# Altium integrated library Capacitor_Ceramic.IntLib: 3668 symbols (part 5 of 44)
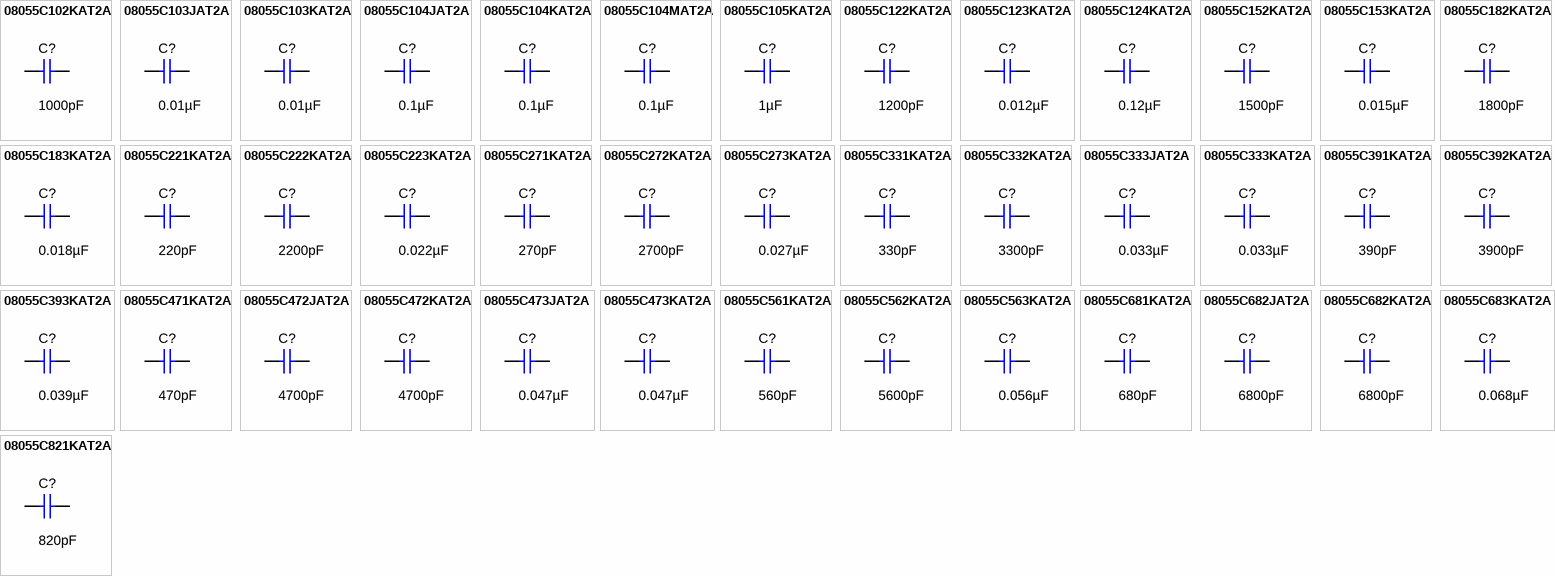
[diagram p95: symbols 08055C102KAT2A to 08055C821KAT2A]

## 08055C681KAT2A
designator C?  ValueDisplayed: 680pF  (hidden comment: 08055C681KAT2A)
CAP, CERM, 680 pF, 50 V,+/- 10%, X7R, 0805; Manufacturer: AVX; Polarized: N; CompType: Capacitor; Value: 680pF; U/M: EA; Cap_F: 0.00000000068; Tolerance_%: 10; ESR_ohm: 0.364; Value1: 0.364 ohm; VDC_V: 50; Value2: 50V; TaMin_C: -55; TaMax_C: 125; Cap_Case: 0805; SizeArea_mm2: 2.5; SizeAreaWB_mm2: 6.75; SizeX_mm: 2; SizeY_mm: 1.25; SizeZ_mm: 1.45; AEC Category: Q200; Green_Lifecycle: Not Set; Green_REACh: Incomplete
signal-integrity model Cap
simulation model Cap
footprint 0805_HV
footprint 0805_HV1
footprint 0805
footprint 0805M
footprint 0805L
pins: 1, 2

## 08055C682JAT2A
designator C?  ValueDisplayed: 6800pF  (hidden comment: 08055C682JAT2A)
CAP, CERM, 6800 pF, 50 V,+/- 5%, X7R, 0805; Manufacturer: AVX; Polarized: N; CompType: Capacitor; Value: 6800pF; U/M: EA; Cap_F: 0.0000000068; Tolerance_%: 5; ESR_ohm: 0.096; Value1: 0.096 ohm; VDC_V: 50; Value2: 50V; TaMin_C: -55; TaMax_C: 125; Cap_Case: 0805; SizeArea_mm2: 2.5; SizeAreaWB_mm2: 6.75; SizeX_mm: 2; SizeY_mm: 1.25; SizeZ_mm: 1.45; AEC Category: Q200; Green_Lifecycle: Not Set; Green_REACh: Incomplete
signal-integrity model Cap
simulation model Cap
footprint 0805_HV
footprint 0805_HV1
footprint 0805
footprint 0805M
footprint 0805L
pins: 1, 2

## 08055C682KAT2A
designator C?  ValueDisplayed: 6800pF  (hidden comment: 08055C682KAT2A)
CAP, CERM, 6800 pF, 50 V,+/- 10%, X7R, 0805; Manufacturer: AVX; Polarized: N; CompType: Capacitor; Value: 6800pF; U/M: EA; Cap_F: 0.0000000068; Tolerance_%: 10; ESR_ohm: 0.096; Value1: 0.096 ohm; VDC_V: 50; Value2: 50V; TaMin_C: -55; TaMax_C: 125; Cap_Case: 0805; SizeArea_mm2: 2.5; SizeAreaWB_mm2: 6.75; SizeX_mm: 2; SizeY_mm: 1.25; SizeZ_mm: 1.45; AEC Category: Q200; Green_Lifecycle: Not Set; Green_REACh: Incomplete
signal-integrity model Cap
simulation model Cap
footprint 0805_HV
footprint 0805_HV1
footprint 0805
footprint 0805M
footprint 0805L
pins: 1, 2

## 08055C683KAT2A
designator C?  ValueDisplayed: 0.068µF  (hidden comment: 08055C683KAT2A)
CAP, CERM, 0.068 µF, 50 V,+/- 10%, X7R, 0805; Manufacturer: AVX; Polarized: N; CompType: Capacitor; Value: 0.068uF; U/M: EA; Cap_F: 0.000000068; Tolerance_%: 10; ESR_ohm: 0.029; Value1: 0.029 ohm; VDC_V: 50; Value2: 50V; TaMin_C: -55; TaMax_C: 125; Cap_Case: 0805; SizeArea_mm2: 2.5; SizeAreaWB_mm2: 6.75; SizeX_mm: 2; SizeY_mm: 1.25; SizeZ_mm: 1.45; AEC Category: Q200; Green_Lifecycle: Not Set; Green_REACh: Incomplete
signal-integrity model Cap
simulation model Cap
footprint 0805_HV
footprint 0805_HV1
footprint 0805
footprint 0805M
footprint 0805L
pins: 1, 2

## 08055C821KAT2A
designator C?  ValueDisplayed: 820pF  (hidden comment: 08055C821KAT2A)
CAP, CERM, 820 pF, 50 V,+/- 10%, X7R, 0805; Manufacturer: AVX; Polarized: N; CompType: Capacitor; Value: 820pF; U/M: EA; Cap_F: 0.00000000082; Tolerance_%: 10; ESR_ohm: 0.326; Value1: 0.326 ohm; VDC_V: 50; Value2: 50V; TaMin_C: -55; TaMax_C: 125; Cap_Case: 0805; SizeArea_mm2: 2.5; SizeAreaWB_mm2: 6.75; SizeX_mm: 2; SizeY_mm: 1.25; SizeZ_mm: 1.45; AEC Category: Q200; Green_Lifecycle: Not Set; Green_REACh: Incomplete
signal-integrity model Cap
simulation model Cap
footprint 0805_HV
footprint 0805_HV1
footprint 0805
footprint 0805M
footprint 0805L
pins: 1, 2

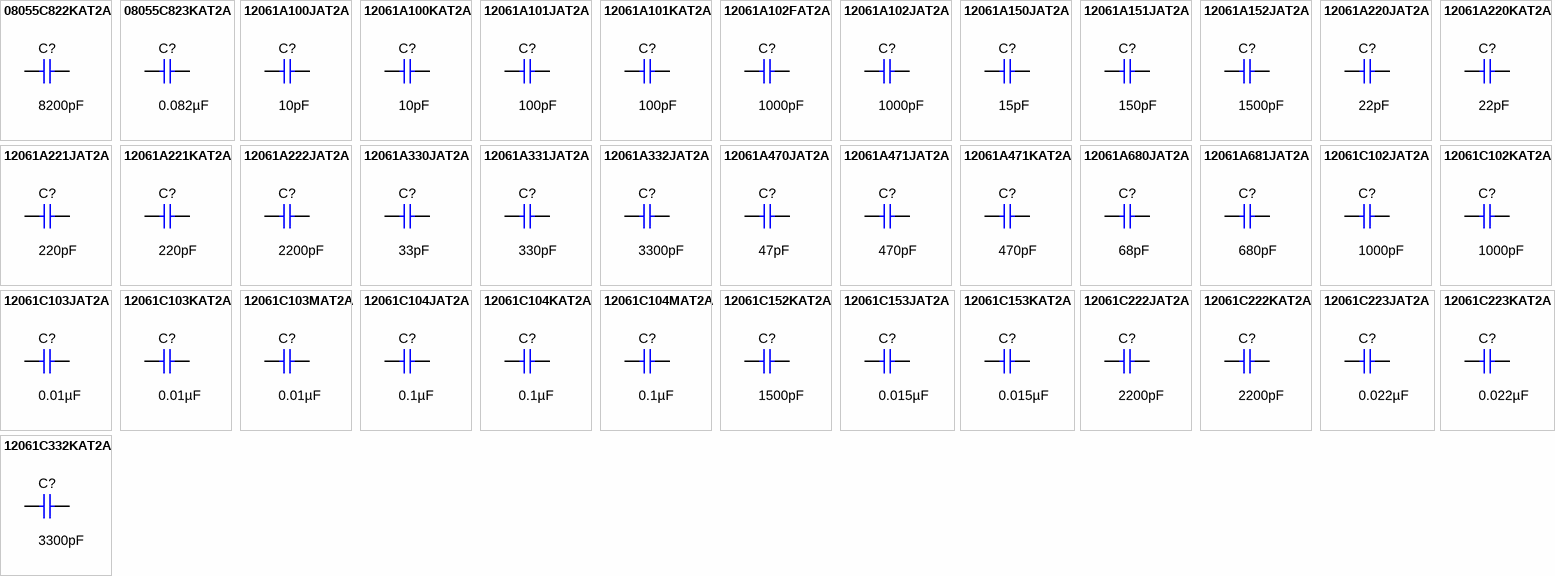
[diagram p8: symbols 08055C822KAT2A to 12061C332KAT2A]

## 08055C822KAT2A
designator C?  ValueDisplayed: 8200pF  (hidden comment: 08055C822KAT2A)
CAP, CERM, 8200 pF, 50 V,+/- 10%, X7R, 0805; Manufacturer: AVX; Polarized: N; CompType: Capacitor; Value: 8200pF; U/M: EA; Cap_F: 0.0000000082; Tolerance_%: 10; ESR_ohm: 0.087; Value1: 0.087 ohm; VDC_V: 50; Value2: 50V; TaMin_C: -55; TaMax_C: 125; Cap_Case: 0805; SizeArea_mm2: 2.5; SizeAreaWB_mm2: 6.75; SizeX_mm: 2; SizeY_mm: 1.25; SizeZ_mm: 1.45; AEC Category: Q200; Green_Lifecycle: Not Set; Green_REACh: Incomplete
signal-integrity model Cap
simulation model Cap
footprint 0805_HV
footprint 0805_HV1
footprint 0805
footprint 0805M
footprint 0805L
pins: 1, 2

## 08055C823KAT2A
designator C?  ValueDisplayed: 0.082µF  (hidden comment: 08055C823KAT2A)
CAP, CERM, 0.082 µF, 50 V,+/- 10%, X7R, 0805; Manufacturer: AVX; Polarized: N; CompType: Capacitor; Value: 0.082uF; U/M: EA; Cap_F: 0.000000082; Tolerance_%: 10; ESR_ohm: 0.026; Value1: 0.026 ohm; VDC_V: 50; Value2: 50V; TaMin_C: -55; TaMax_C: 125; Cap_Case: 0805; SizeArea_mm2: 2.5; SizeAreaWB_mm2: 6.75; SizeX_mm: 2; SizeY_mm: 1.25; SizeZ_mm: 1.45; AEC Category: Q200; Green_Lifecycle: Active; Green_REACh: Passed
signal-integrity model Cap
simulation model Cap
footprint 0805_HV
footprint 0805_HV1
footprint 0805
footprint 0805M
footprint 0805L
pins: 1, 2

## 12061A100JAT2A
designator C?  ValueDisplayed: 10pF  (hidden comment: 12061A100JAT2A)
CAP, CERM, 10 pF, 100 V,+/- 5%, C0G/NP0, 1206; Manufacturer: AVX; Polarized: N; CompType: Capacitor; Value: 10pF; U/M: EA; Cap_F: 0.00000000001; Tolerance_%: 5; ESR_ohm: 2.925; Value1: 2.925 ohm; VDC_V: 100; Value2: 100V; TaMin_C: -55; TaMax_C: 125; Cap_Case: 1206; SizeArea_mm2: 5.12; SizeAreaWB_mm2: 10.92; SizeX_mm: 3.2; SizeY_mm: 1.6; SizeZ_mm: 1.35; AEC Category: Q200; Green_Lifecycle: Not Set; Green_REACh: Incomplete
signal-integrity model Cap
simulation model Cap
footprint 1206
footprint 1206M
footprint 1206L
pins: 1, 2

## 12061A100KAT2A
designator C?  ValueDisplayed: 10pF  (hidden comment: 12061A100KAT2A)
CAP, CERM, 10 pF, 100 V,+/- 10%, C0G/NP0, 1206; Manufacturer: AVX; Polarized: N; CompType: Capacitor; Value: 10pF; U/M: EA; Cap_F: 0.00000000001; Tolerance_%: 10; ESR_ohm: 2.925; Value1: 2.925 ohm; VDC_V: 100; Value2: 100V; TaMin_C: -55; TaMax_C: 125; Cap_Case: 1206; SizeArea_mm2: 5.12; SizeAreaWB_mm2: 10.92; SizeX_mm: 3.2; SizeY_mm: 1.6; SizeZ_mm: 1.35; AEC Category: Q200; Green_Lifecycle: Not Set; Green_REACh: Incomplete
signal-integrity model Cap
simulation model Cap
footprint 1206
footprint 1206M
footprint 1206L
pins: 1, 2

## 12061A101JAT2A
designator C?  ValueDisplayed: 100pF  (hidden comment: 12061A101JAT2A)
CAP, CERM, 100 pF, 100 V,+/- 5%, C0G/NP0, 1206; Manufacturer: AVX; Polarized: N; CompType: Capacitor; Value: 100pF; U/M: EA; Cap_F: 0.0000000001; Tolerance_%: 5; ESR_ohm: 0.701; Value1: 0.701 ohm; VDC_V: 100; Value2: 100V; TaMin_C: -55; TaMax_C: 125; Cap_Case: 1206; SizeArea_mm2: 5.12; SizeAreaWB_mm2: 10.92; SizeX_mm: 3.2; SizeY_mm: 1.6; SizeZ_mm: 1.35; AEC Category: Q200; Green_Lifecycle: Active; Green_REACh: Passed
signal-integrity model Cap
simulation model Cap
footprint 1206
footprint 1206M
footprint 1206L
pins: 1, 2

## 12061A101KAT2A
designator C?  ValueDisplayed: 100pF  (hidden comment: 12061A101KAT2A)
CAP, CERM, 100 pF, 100 V,+/- 10%, C0G/NP0, 1206; Manufacturer: AVX; Polarized: N; CompType: Capacitor; Value: 100pF; U/M: EA; Cap_F: 0.0000000001; Tolerance_%: 10; ESR_ohm: 0.701; Value1: 0.701 ohm; VDC_V: 100; Value2: 100V; TaMin_C: -55; TaMax_C: 125; Cap_Case: 1206; SizeArea_mm2: 5.12; SizeAreaWB_mm2: 10.92; SizeX_mm: 3.2; SizeY_mm: 1.6; SizeZ_mm: 1.35; AEC Category: Q200; Green_Lifecycle: Not Set; Green_REACh: Incomplete
signal-integrity model Cap
simulation model Cap
footprint 1206
footprint 1206M
footprint 1206L
pins: 1, 2

## 12061A102FAT2A
designator C?  ValueDisplayed: 1000pF  (hidden comment: 12061A102FAT2A)
CAP, CERM, 1000 pF, 100 V,+/- 1%, C0G/NP0, 1206; Manufacturer: AVX; Polarized: N; CompType: Capacitor; Value: 1000pF; U/M: EA; Cap_F: 0.000000001; Tolerance_%: 1; ESR_ohm: 0.238; Value1: 0.238 ohm; VDC_V: 100; Value2: 100V; TaMin_C: -55; TaMax_C: 125; Cap_Case: 1206; SizeArea_mm2: 5.12; SizeAreaWB_mm2: 10.92; SizeX_mm: 3.2; SizeY_mm: 1.6; SizeZ_mm: 1.35; AEC Category: Q200; Green_Lifecycle: Not Set; Green_REACh: Incomplete
signal-integrity model Cap
simulation model Cap
footprint 1206
footprint 1206M
footprint 1206L
pins: 1, 2

## 12061A102JAT2A
designator C?  ValueDisplayed: 1000pF  (hidden comment: 12061A102JAT2A)
CAP, CERM, 1000 pF, 100 V,+/- 5%, C0G/NP0, 1206; Manufacturer: AVX; Polarized: N; CompType: Capacitor; Value: 1000pF; U/M: EA; Cap_F: 0.000000001; Tolerance_%: 5; ESR_ohm: 0.238; Value1: 0.238 ohm; VDC_V: 100; Value2: 100V; TaMin_C: -55; TaMax_C: 125; Cap_Case: 1206; SizeArea_mm2: 5.12; SizeAreaWB_mm2: 10.92; SizeX_mm: 3.2; SizeY_mm: 1.6; SizeZ_mm: 1.35; AEC Category: Q200; Green_Lifecycle: Active; Green_REACh: Passed
signal-integrity model Cap
simulation model Cap
footprint 1206
footprint 1206M
footprint 1206L
pins: 1, 2

## 12061A150JAT2A
designator C?  ValueDisplayed: 15pF  (hidden comment: 12061A150JAT2A)
CAP, CERM, 15 pF, 100 V,+/- 5%, C0G/NP0, 1206; Manufacturer: AVX; Polarized: N; CompType: Capacitor; Value: 15pF; U/M: EA; Cap_F: 0.000000000015; Tolerance_%: 5; ESR_ohm: 2.241; Value1: 2.241 ohm; VDC_V: 100; Value2: 100V; TaMin_C: -55; TaMax_C: 125; Cap_Case: 1206; SizeArea_mm2: 5.12; SizeAreaWB_mm2: 10.92; SizeX_mm: 3.2; SizeY_mm: 1.6; SizeZ_mm: 1.35; AEC Category: Q200; Green_Lifecycle: Not Set; Green_REACh: Incomplete
signal-integrity model Cap
simulation model Cap
footprint 1206
footprint 1206M
footprint 1206L
pins: 1, 2

## 12061A151JAT2A
designator C?  ValueDisplayed: 150pF  (hidden comment: 12061A151JAT2A)
CAP, CERM, 150 pF, 100 V,+/- 5%, C0G/NP0, 1206; Manufacturer: AVX; Polarized: N; CompType: Capacitor; Value: 150pF; U/M: EA; Cap_F: 0.00000000015; Tolerance_%: 5; ESR_ohm: 0.573; Value1: 0.573 ohm; VDC_V: 100; Value2: 100V; TaMin_C: -55; TaMax_C: 125; Cap_Case: 1206; SizeArea_mm2: 5.12; SizeAreaWB_mm2: 10.92; SizeX_mm: 3.2; SizeY_mm: 1.6; SizeZ_mm: 1.35; AEC Category: Q200; Green_Lifecycle: Not Set; Green_REACh: Incomplete
signal-integrity model Cap
simulation model Cap
footprint 1206
footprint 1206M
footprint 1206L
pins: 1, 2

## 12061A152JAT2A
designator C?  ValueDisplayed: 1500pF  (hidden comment: 12061A152JAT2A)
CAP, CERM, 1500 pF, 100 V,+/- 5%, C0G/NP0, 1206; Manufacturer: AVX; Polarized: N; CompType: Capacitor; Value: 1500pF; U/M: EA; Cap_F: 0.0000000015; Tolerance_%: 5; ESR_ohm: 0.201; Value1: 0.201 ohm; VDC_V: 100; Value2: 100V; TaMin_C: -55; TaMax_C: 125; Cap_Case: 1206; SizeArea_mm2: 5.12; SizeAreaWB_mm2: 10.92; SizeX_mm: 3.2; SizeY_mm: 1.6; SizeZ_mm: 1.35; AEC Category: Q200; Green_Lifecycle: Not Set; Green_REACh: Incomplete
signal-integrity model Cap
simulation model Cap
footprint 1206
footprint 1206M
footprint 1206L
pins: 1, 2

## 12061A220JAT2A
designator C?  ValueDisplayed: 22pF  (hidden comment: 12061A220JAT2A)
CAP, CERM, 22 pF, 100 V,+/- 5%, C0G/NP0, 1206; Manufacturer: AVX; Polarized: N; CompType: Capacitor; Value: 22pF; U/M: EA; Cap_F: 0.000000000022; Tolerance_%: 5; ESR_ohm: 1.753; Value1: 1.753 ohm; VDC_V: 100; Value2: 100V; TaMin_C: -55; TaMax_C: 125; Cap_Case: 1206; SizeArea_mm2: 5.12; SizeAreaWB_mm2: 10.92; SizeX_mm: 3.2; SizeY_mm: 1.6; SizeZ_mm: 1.35; AEC Category: Q200; Green_Lifecycle: Not Set; Green_REACh: Incomplete
signal-integrity model Cap
simulation model Cap
footprint 1206
footprint 1206M
footprint 1206L
pins: 1, 2

## 12061A220KAT2A
designator C?  ValueDisplayed: 22pF  (hidden comment: 12061A220KAT2A)
CAP, CERM, 22 pF, 100 V,+/- 10%, C0G/NP0, 1206; Manufacturer: AVX; Polarized: N; CompType: Capacitor; Value: 22pF; U/M: EA; Cap_F: 0.000000000022; Tolerance_%: 10; ESR_ohm: 1.753; Value1: 1.753 ohm; VDC_V: 100; Value2: 100V; TaMin_C: -55; TaMax_C: 125; Cap_Case: 1206; SizeArea_mm2: 5.12; SizeAreaWB_mm2: 10.92; SizeX_mm: 3.2; SizeY_mm: 1.6; SizeZ_mm: 1.35; AEC Category: Q200; Green_Lifecycle: Not Set; Green_REACh: Incomplete
signal-integrity model Cap
simulation model Cap
footprint 1206
footprint 1206M
footprint 1206L
pins: 1, 2

## 12061A221JAT2A
designator C?  ValueDisplayed: 220pF  (hidden comment: 12061A221JAT2A)
CAP, CERM, 220 pF, 100 V,+/- 5%, C0G/NP0, 1206; Manufacturer: AVX; Polarized: N; CompType: Capacitor; Value: 220pF; U/M: EA; Cap_F: 0.00000000022; Tolerance_%: 5; ESR_ohm: 0.475; Value1: 0.475 ohm; VDC_V: 100; Value2: 100V; TaMin_C: -55; TaMax_C: 125; Cap_Case: 1206; SizeArea_mm2: 5.12; SizeAreaWB_mm2: 10.92; SizeX_mm: 3.2; SizeY_mm: 1.6; SizeZ_mm: 1.35; AEC Category: Q200; Green_Lifecycle: Active; Green_REACh: Passed
signal-integrity model Cap
simulation model Cap
footprint 1206
footprint 1206M
footprint 1206L
pins: 1, 2

## 12061A221KAT2A
designator C?  ValueDisplayed: 220pF  (hidden comment: 12061A221KAT2A)
CAP, CERM, 220 pF, 100 V,+/- 10%, C0G/NP0, 1206; Manufacturer: AVX; Polarized: N; CompType: Capacitor; Value: 220pF; U/M: EA; Cap_F: 0.00000000022; Tolerance_%: 10; ESR_ohm: 0.475; Value1: 0.475 ohm; VDC_V: 100; Value2: 100V; TaMin_C: -55; TaMax_C: 125; Cap_Case: 1206; SizeArea_mm2: 5.12; SizeAreaWB_mm2: 10.92; SizeX_mm: 3.2; SizeY_mm: 1.6; SizeZ_mm: 1.35; AEC Category: Q200; Green_Lifecycle: Not Set; Green_REACh: Incomplete
signal-integrity model Cap
simulation model Cap
footprint 1206
footprint 1206M
footprint 1206L
pins: 1, 2

## 12061A222JAT2A
designator C?  ValueDisplayed: 2200pF  (hidden comment: 12061A222JAT2A)
CAP, CERM, 2200 pF, 100 V,+/- 5%, C0G/NP0, 1206; Manufacturer: AVX; Polarized: N; CompType: Capacitor; Value: 2200pF; U/M: EA; Cap_F: 0.0000000022; Tolerance_%: 5; ESR_ohm: 0.173; Value1: 0.173 ohm; VDC_V: 100; Value2: 100V; TaMin_C: -55; TaMax_C: 125; Cap_Case: 1206; SizeArea_mm2: 5.12; SizeAreaWB_mm2: 10.92; SizeX_mm: 3.2; SizeY_mm: 1.6; SizeZ_mm: 1.35; AEC Category: Q200; Green_Lifecycle: Not Set; Green_REACh: Incomplete
signal-integrity model Cap
simulation model Cap
footprint 1206
footprint 1206M
footprint 1206L
pins: 1, 2

## 12061A330JAT2A
designator C?  ValueDisplayed: 33pF  (hidden comment: 12061A330JAT2A)
CAP, CERM, 33 pF, 100 V,+/- 5%, C0G/NP0, 1206; Manufacturer: AVX; Polarized: N; CompType: Capacitor; Value: 33pF; U/M: EA; Cap_F: 0.000000000033; Tolerance_%: 5; ESR_ohm: 1.359; Value1: 1.359 ohm; VDC_V: 100; Value2: 100V; TaMin_C: -55; TaMax_C: 125; Cap_Case: 1206; SizeArea_mm2: 5.12; SizeAreaWB_mm2: 10.92; SizeX_mm: 3.2; SizeY_mm: 1.6; SizeZ_mm: 1.35; AEC Category: Q200; Green_Lifecycle: Not Set; Green_REACh: Incomplete
signal-integrity model Cap
simulation model Cap
footprint 1206
footprint 1206M
footprint 1206L
pins: 1, 2

## 12061A331JAT2A
designator C?  ValueDisplayed: 330pF  (hidden comment: 12061A331JAT2A)
CAP, CERM, 330 pF, 100 V,+/- 5%, C0G/NP0, 1206; Manufacturer: AVX; Polarized: N; CompType: Capacitor; Value: 330pF; U/M: EA; Cap_F: 0.00000000033; Tolerance_%: 5; ESR_ohm: 0.392; Value1: 0.392 ohm; VDC_V: 100; Value2: 100V; TaMin_C: -55; TaMax_C: 125; Cap_Case: 1206; SizeArea_mm2: 5.12; SizeAreaWB_mm2: 10.92; SizeX_mm: 3.2; SizeY_mm: 1.6; SizeZ_mm: 1.35; AEC Category: Q200; Green_Lifecycle: Not Set; Green_REACh: Incomplete
signal-integrity model Cap
simulation model Cap
footprint 1206
footprint 1206M
footprint 1206L
pins: 1, 2

## 12061A332JAT2A
designator C?  ValueDisplayed: 3300pF  (hidden comment: 12061A332JAT2A)
CAP, CERM, 3300 pF, 100 V,+/- 5%, C0G/NP0, 1206; Manufacturer: AVX; Polarized: N; CompType: Capacitor; Value: 3300pF; U/M: EA; Cap_F: 0.0000000033; Tolerance_%: 5; ESR_ohm: 0.149; Value1: 0.149 ohm; VDC_V: 100; Value2: 100V; TaMin_C: -55; TaMax_C: 125; Cap_Case: 1206; SizeArea_mm2: 5.12; SizeAreaWB_mm2: 10.92; SizeX_mm: 3.2; SizeY_mm: 1.6; SizeZ_mm: 1.35; AEC Category: Q200; Green_Lifecycle: Not Set; Green_REACh: Incomplete
signal-integrity model Cap
simulation model Cap
footprint 1206
footprint 1206M
footprint 1206L
pins: 1, 2

## 12061A470JAT2A
designator C?  ValueDisplayed: 47pF  (hidden comment: 12061A470JAT2A)
CAP, CERM, 47 pF, 100 V,+/- 5%, C0G/NP0, 1206; Manufacturer: AVX; Polarized: N; CompType: Capacitor; Value: 47pF; U/M: EA; Cap_F: 0.000000000047; Tolerance_%: 5; ESR_ohm: 1.093; Value1: 1.093 ohm; VDC_V: 100; Value2: 100V; TaMin_C: -55; TaMax_C: 125; Cap_Case: 1206; SizeArea_mm2: 5.12; SizeAreaWB_mm2: 10.92; SizeX_mm: 3.2; SizeY_mm: 1.6; SizeZ_mm: 1.35; AEC Category: Q200; Green_Lifecycle: Not Set; Green_REACh: Incomplete
signal-integrity model Cap
simulation model Cap
footprint 1206
footprint 1206M
footprint 1206L
pins: 1, 2

## 12061A471JAT2A
designator C?  ValueDisplayed: 470pF  (hidden comment: 12061A471JAT2A)
CAP, CERM, 470 pF, 100 V,+/- 5%, C0G/NP0, 1206; Manufacturer: AVX; Polarized: N; CompType: Capacitor; Value: 470pF; U/M: EA; Cap_F: 0.00000000047; Tolerance_%: 5; ESR_ohm: 0.332; Value1: 0.332 ohm; VDC_V: 100; Value2: 100V; TaMin_C: -55; TaMax_C: 125; Cap_Case: 1206; SizeArea_mm2: 5.12; SizeAreaWB_mm2: 10.92; SizeX_mm: 3.2; SizeY_mm: 1.6; SizeZ_mm: 1.35; AEC Category: Q200; Green_Lifecycle: Not Set; Green_REACh: Incomplete
signal-integrity model Cap
simulation model Cap
footprint 1206
footprint 1206M
footprint 1206L
pins: 1, 2

## 12061A471KAT2A
designator C?  ValueDisplayed: 470pF  (hidden comment: 12061A471KAT2A)
CAP, CERM, 470 pF, 100 V,+/- 10%, C0G/NP0, 1206; Manufacturer: AVX; Polarized: N; CompType: Capacitor; Value: 470pF; U/M: EA; Cap_F: 0.00000000047; Tolerance_%: 10; ESR_ohm: 0.332; Value1: 0.332 ohm; VDC_V: 100; Value2: 100V; TaMin_C: -55; TaMax_C: 125; Cap_Case: 1206; SizeArea_mm2: 5.12; SizeAreaWB_mm2: 10.92; SizeX_mm: 3.2; SizeY_mm: 1.6; SizeZ_mm: 1.35; AEC Category: Q200; Green_Lifecycle: Active; Green_REACh: Passed
signal-integrity model Cap
simulation model Cap
footprint 1206
footprint 1206M
footprint 1206L
pins: 1, 2

## 12061A680JAT2A
designator C?  ValueDisplayed: 68pF  (hidden comment: 12061A680JAT2A)
CAP, CERM, 68 pF, 100 V,+/- 5%, C0G/NP0, 1206; Manufacturer: AVX; Polarized: N; CompType: Capacitor; Value: 68pF; U/M: EA; Cap_F: 0.000000000068; Tolerance_%: 5; ESR_ohm: 0.874; Value1: 0.874 ohm; VDC_V: 100; Value2: 100V; TaMin_C: -55; TaMax_C: 125; Cap_Case: 1206; SizeArea_mm2: 5.12; SizeAreaWB_mm2: 10.92; SizeX_mm: 3.2; SizeY_mm: 1.6; SizeZ_mm: 1.35; AEC Category: Q200; Green_Lifecycle: Not Set; Green_REACh: Incomplete
signal-integrity model Cap
simulation model Cap
footprint 1206
footprint 1206M
footprint 1206L
pins: 1, 2

## 12061A681JAT2A
designator C?  ValueDisplayed: 680pF  (hidden comment: 12061A681JAT2A)
CAP, CERM, 680 pF, 100 V,+/- 5%, C0G/NP0, 1206; Manufacturer: AVX; Polarized: N; CompType: Capacitor; Value: 680pF; U/M: EA; Cap_F: 0.00000000068; Tolerance_%: 5; ESR_ohm: 0.281; Value1: 0.281 ohm; VDC_V: 100; Value2: 100V; TaMin_C: -55; TaMax_C: 125; Cap_Case: 1206; SizeArea_mm2: 5.12; SizeAreaWB_mm2: 10.92; SizeX_mm: 3.2; SizeY_mm: 1.6; SizeZ_mm: 1.35; AEC Category: Q200; Green_Lifecycle: Not Set; Green_REACh: Incomplete
signal-integrity model Cap
simulation model Cap
footprint 1206
footprint 1206M
footprint 1206L
pins: 1, 2

## 12061C102JAT2A
designator C?  ValueDisplayed: 1000pF  (hidden comment: 12061C102JAT2A)
CAP, CERM, 1000 pF, 100 V,+/- 5%, X7R, 1206; Manufacturer: AVX; Polarized: N; CompType: Capacitor; Value: 1000pF; U/M: EA; Cap_F: 0.000000001; Tolerance_%: 5; ESR_ohm: 0.427; Value1: 0.427 ohm; VDC_V: 100; Value2: 100V; TaMin_C: -55; TaMax_C: 125; Cap_Case: 1206; SizeArea_mm2: 5.12; SizeAreaWB_mm2: 10.92; SizeX_mm: 3.2; SizeY_mm: 1.6; SizeZ_mm: 1.35; AEC Category: Q200; Green_Lifecycle: Not Set; Green_REACh: Incomplete
signal-integrity model Cap
simulation model Cap
footprint 1206
footprint 1206M
footprint 1206L
pins: 1, 2

## 12061C102KAT2A
designator C?  ValueDisplayed: 1000pF  (hidden comment: 12061C102KAT2A)
CAP, CERM, 1000 pF, 100 V,+/- 10%, X7R, 1206; Manufacturer: AVX; Polarized: N; CompType: Capacitor; Value: 1000pF; U/M: EA; Cap_F: 0.000000001; Tolerance_%: 10; ESR_ohm: 0.427; Value1: 0.427 ohm; VDC_V: 100; Value2: 100V; TaMin_C: -55; TaMax_C: 125; Cap_Case: 1206; SizeArea_mm2: 5.12; SizeAreaWB_mm2: 10.92; SizeX_mm: 3.2; SizeY_mm: 1.6; SizeZ_mm: 1.35; AEC Category: Q200; Green_Lifecycle: Active; Green_REACh: Passed
signal-integrity model Cap
simulation model Cap
footprint 1206
footprint 1206M
footprint 1206L
pins: 1, 2

## 12061C103JAT2A
designator C?  ValueDisplayed: 0.01µF  (hidden comment: 12061C103JAT2A)
CAP, CERM, 0.01 µF, 100 V,+/- 5%, X7R, 1206; Manufacturer: AVX; Polarized: N; CompType: Capacitor; Value: 0.01uF; U/M: EA; Cap_F: 0.00000001; Tolerance_%: 5; ESR_ohm: 0.119; Value1: 0.119 ohm; VDC_V: 100; Value2: 100V; TaMin_C: -55; TaMax_C: 125; Cap_Case: 1206; SizeArea_mm2: 5.12; SizeAreaWB_mm2: 10.92; SizeX_mm: 3.2; SizeY_mm: 1.6; SizeZ_mm: 1.35; AEC Category: Q200; Green_Lifecycle: Not Set; Green_REACh: Incomplete
signal-integrity model Cap
simulation model Cap
footprint 1206
footprint 1206M
footprint 1206L
pins: 1, 2

## 12061C103KAT2A
designator C?  ValueDisplayed: 0.01µF  (hidden comment: 12061C103KAT2A)
CAP, CERM, 0.01 µF, 100 V,+/- 10%, X7R, 1206; Manufacturer: AVX; Polarized: N; CompType: Capacitor; Value: 0.01uF; U/M: EA; Cap_F: 0.00000001; Tolerance_%: 10; ESR_ohm: 0.119; Value1: 0.119 ohm; VDC_V: 100; Value2: 100V; TaMin_C: -55; TaMax_C: 125; Cap_Case: 1206; SizeArea_mm2: 5.12; SizeAreaWB_mm2: 10.92; SizeX_mm: 3.2; SizeY_mm: 1.6; SizeZ_mm: 1.35; AEC Category: Q200; Green_Lifecycle: Not Set; Green_REACh: Incomplete
signal-integrity model Cap
simulation model Cap
footprint 1206
footprint 1206M
footprint 1206L
pins: 1, 2

## 12061C103MAT2A
designator C?  ValueDisplayed: 0.01µF  (hidden comment: 12061C103MAT2A)
CAP, CERM, 0.01 µF, 100 V,+/- 20%, X7R, 1206; Manufacturer: AVX; Polarized: N; CompType: Capacitor; Value: 0.01uF; U/M: EA; Cap_F: 0.00000001; Tolerance_%: 20; ESR_ohm: 0.119; Value1: 0.119 ohm; VDC_V: 100; Value2: 100V; TaMin_C: -55; TaMax_C: 125; Cap_Case: 1206; SizeArea_mm2: 5.12; SizeAreaWB_mm2: 10.92; SizeX_mm: 3.2; SizeY_mm: 1.6; SizeZ_mm: 1.35; AEC Category: Q200; Green_Lifecycle: Not Set; Green_REACh: Incomplete
signal-integrity model Cap
simulation model Cap
footprint 1206
footprint 1206M
footprint 1206L
pins: 1, 2

## 12061C104JAT2A
designator C?  ValueDisplayed: 0.1µF  (hidden comment: 12061C104JAT2A)
CAP, CERM, 0.1 µF, 100 V,+/- 5%, X7R, 1206; Manufacturer: AVX; Polarized: N; CompType: Capacitor; Value: 0.1uF; U/M: EA; Cap_F: 0.0000001; Tolerance_%: 5; ESR_ohm: 0.037; Value1: 0.037 ohm; VDC_V: 100; Value2: 100V; TaMin_C: -55; TaMax_C: 125; Cap_Case: 1206; SizeArea_mm2: 5.12; SizeAreaWB_mm2: 10.92; SizeX_mm: 3.2; SizeY_mm: 1.6; SizeZ_mm: 1.35; AEC Category: Q200; Green_Lifecycle: Active; Green_REACh: Passed
signal-integrity model Cap
simulation model Cap
footprint 1206
footprint 1206M
footprint 1206L
pins: 1, 2

## 12061C104KAT2A
designator C?  ValueDisplayed: 0.1µF  (hidden comment: 12061C104KAT2A)
CAP, CERM, 0.1 µF, 100 V,+/- 10%, X7R, 1206; Manufacturer: AVX; Polarized: N; CompType: Capacitor; Value: 0.1uF; U/M: EA; Cap_F: 0.0000001; Tolerance_%: 10; ESR_ohm: 0.037; Value1: 0.037 ohm; VDC_V: 100; Value2: 100V; TaMin_C: -55; TaMax_C: 125; Cap_Case: 1206; SizeArea_mm2: 5.12; SizeAreaWB_mm2: 10.92; SizeX_mm: 3.2; SizeY_mm: 1.6; SizeZ_mm: 1.35; AEC Category: Q200; Green_Lifecycle: Active; Green_REACh: Passed
signal-integrity model Cap
simulation model Cap
footprint 1206
footprint 1206M
footprint 1206L
pins: 1, 2

## 12061C104MAT2A
designator C?  ValueDisplayed: 0.1µF  (hidden comment: 12061C104MAT2A)
CAP, CERM, 0.1 µF, 100 V,+/- 20%, X7R, 1206; Manufacturer: AVX; Polarized: N; CompType: Capacitor; Value: 0.1uF; U/M: EA; Cap_F: 0.0000001; Tolerance_%: 20; ESR_ohm: 0.037; Value1: 0.037 ohm; VDC_V: 100; Value2: 100V; TaMin_C: -55; TaMax_C: 125; Cap_Case: 1206; SizeArea_mm2: 5.12; SizeAreaWB_mm2: 10.92; SizeX_mm: 3.2; SizeY_mm: 1.6; SizeZ_mm: 1.35; AEC Category: Q200; Green_Lifecycle: Active; Green_REACh: Passed
signal-integrity model Cap
simulation model Cap
footprint 1206
footprint 1206M
footprint 1206L
pins: 1, 2

## 12061C152KAT2A
designator C?  ValueDisplayed: 1500pF  (hidden comment: 12061C152KAT2A)
CAP, CERM, 1500 pF, 100 V,+/- 10%, X7R, 1206; Manufacturer: AVX; Polarized: N; CompType: Capacitor; Value: 1500pF; U/M: EA; Cap_F: 0.0000000015; Tolerance_%: 10; ESR_ohm: 0.338; Value1: 0.338 ohm; VDC_V: 100; Value2: 100V; TaMin_C: -55; TaMax_C: 125; Cap_Case: 1206; SizeArea_mm2: 5.12; SizeAreaWB_mm2: 10.92; SizeX_mm: 3.2; SizeY_mm: 1.6; SizeZ_mm: 1.35; AEC Category: Q200; Green_Lifecycle: Not Set; Green_REACh: Incomplete
signal-integrity model Cap
simulation model Cap
footprint 1206
footprint 1206M
footprint 1206L
pins: 1, 2

## 12061C153JAT2A
designator C?  ValueDisplayed: 0.015µF  (hidden comment: 12061C153JAT2A)
CAP, CERM, 0.015 µF, 100 V,+/- 5%, X7R, 1206; Manufacturer: AVX; Polarized: N; CompType: Capacitor; Value: 0.015uF; U/M: EA; Cap_F: 0.000000015; Tolerance_%: 5; ESR_ohm: 0.096; Value1: 0.096 ohm; VDC_V: 100; Value2: 100V; TaMin_C: -55; TaMax_C: 125; Cap_Case: 1206; SizeArea_mm2: 5.12; SizeAreaWB_mm2: 10.92; SizeX_mm: 3.2; SizeY_mm: 1.6; SizeZ_mm: 1.35; AEC Category: Q200; Green_Lifecycle: Not Set; Green_REACh: Incomplete
signal-integrity model Cap
simulation model Cap
footprint 1206
footprint 1206M
footprint 1206L
pins: 1, 2

## 12061C153KAT2A
designator C?  ValueDisplayed: 0.015µF  (hidden comment: 12061C153KAT2A)
CAP, CERM, 0.015 µF, 100 V,+/- 10%, X7R, 1206; Manufacturer: AVX; Polarized: N; CompType: Capacitor; Value: 0.015uF; U/M: EA; Cap_F: 0.000000015; Tolerance_%: 10; ESR_ohm: 0.095; Value1: 0.095 ohm; VDC_V: 100; Value2: 100V; IRMS_A: 0.6; TaMin_C: -55; TaMax_C: 125; Cap_Case: 1206; SizeArea_mm2: 5.12; SizeAreaWB_mm2: 10.92; SizeX_mm: 3.2; SizeY_mm: 1.6; SizeZ_mm: 1.35; AEC Category: Q200; Green_Lifecycle: Not Set; Green_REACh: Incomplete
signal-integrity model Cap
simulation model Cap
footprint 1206
footprint 1206M
footprint 1206L
pins: 1, 2

## 12061C222JAT2A
designator C?  ValueDisplayed: 2200pF  (hidden comment: 12061C222JAT2A)
CAP, CERM, 2200 pF, 100 V,+/- 5%, X7R, 1206; Manufacturer: AVX; Polarized: N; CompType: Capacitor; Value: 2200pF; U/M: EA; Cap_F: 0.0000000022; Tolerance_%: 5; ESR_ohm: 0.272; Value1: 0.272 ohm; VDC_V: 100; Value2: 100V; TaMin_C: -55; TaMax_C: 125; Cap_Case: 1206; SizeArea_mm2: 5.12; SizeAreaWB_mm2: 10.92; SizeX_mm: 3.2; SizeY_mm: 1.6; SizeZ_mm: 1.35; AEC Category: Q200; Green_Lifecycle: Not Set; Green_REACh: Incomplete
signal-integrity model Cap
simulation model Cap
footprint 1206
footprint 1206M
footprint 1206L
pins: 1, 2

## 12061C222KAT2A
designator C?  ValueDisplayed: 2200pF  (hidden comment: 12061C222KAT2A)
CAP, CERM, 2200 pF, 100 V,+/- 10%, X7R, 1206; Manufacturer: AVX; Polarized: N; CompType: Capacitor; Value: 2200pF; U/M: EA; Cap_F: 0.0000000022; Tolerance_%: 10; ESR_ohm: 0.272; Value1: 0.272 ohm; VDC_V: 100; Value2: 100V; TaMin_C: -55; TaMax_C: 125; Cap_Case: 1206; SizeArea_mm2: 5.12; SizeAreaWB_mm2: 10.92; SizeX_mm: 3.2; SizeY_mm: 1.6; SizeZ_mm: 1.35; AEC Category: Q200; Green_Lifecycle: Not Set; Green_REACh: Incomplete
signal-integrity model Cap
simulation model Cap
footprint 1206
footprint 1206M
footprint 1206L
pins: 1, 2

## 12061C223JAT2A
designator C?  ValueDisplayed: 0.022µF  (hidden comment: 12061C223JAT2A)
CAP, CERM, 0.022 µF, 100 V,+/- 5%, X7R, 1206; Manufacturer: AVX; Polarized: N; CompType: Capacitor; Value: 0.022uF; U/M: EA; Cap_F: 0.000000022; Tolerance_%: 5; ESR_ohm: 0.079; Value1: 0.079 ohm; VDC_V: 100; Value2: 100V; TaMin_C: -55; TaMax_C: 125; Cap_Case: 1206; SizeArea_mm2: 5.12; SizeAreaWB_mm2: 10.92; SizeX_mm: 3.2; SizeY_mm: 1.6; SizeZ_mm: 1.35; AEC Category: Q200; Green_Lifecycle: Active; Green_REACh: Passed
signal-integrity model Cap
simulation model Cap
footprint 1206
footprint 1206M
footprint 1206L
pins: 1, 2

## 12061C223KAT2A
designator C?  ValueDisplayed: 0.022µF  (hidden comment: 12061C223KAT2A)
CAP, CERM, 0.022 µF, 100 V,+/- 10%, X7R, 1206; Manufacturer: AVX; Polarized: N; CompType: Capacitor; Value: 0.022uF; U/M: EA; Cap_F: 0.000000022; Tolerance_%: 10; ESR_ohm: 0.079; Value1: 0.079 ohm; VDC_V: 100; Value2: 100V; TaMin_C: -55; TaMax_C: 125; Cap_Case: 1206; SizeArea_mm2: 5.12; SizeAreaWB_mm2: 10.92; SizeX_mm: 3.2; SizeY_mm: 1.6; SizeZ_mm: 1.35; AEC Category: Q200; Green_Lifecycle: Not Set; Green_REACh: Incomplete
signal-integrity model Cap
simulation model Cap
footprint 1206
footprint 1206M
footprint 1206L
pins: 1, 2

## 12061C332KAT2A
designator C?  ValueDisplayed: 3300pF  (hidden comment: 12061C332KAT2A)
CAP, CERM, 3300 pF, 100 V,+/- 10%, X7R, 1206; Manufacturer: AVX; Polarized: N; CompType: Capacitor; Value: 3300pF; U/M: EA; Cap_F: 0.0000000033; Tolerance_%: 10; ESR_ohm: 0.216; Value1: 0.216 ohm; VDC_V: 100; Value2: 100V; TaMin_C: -55; TaMax_C: 125; Cap_Case: 1206; SizeArea_mm2: 5.12; SizeAreaWB_mm2: 10.92; SizeX_mm: 3.2; SizeY_mm: 1.6; SizeZ_mm: 1.35; AEC Category: Q200; Green_Lifecycle: Not Set; Green_REACh: Incomplete
signal-integrity model Cap
simulation model Cap
footprint 1206
footprint 1206M
footprint 1206L
pins: 1, 2

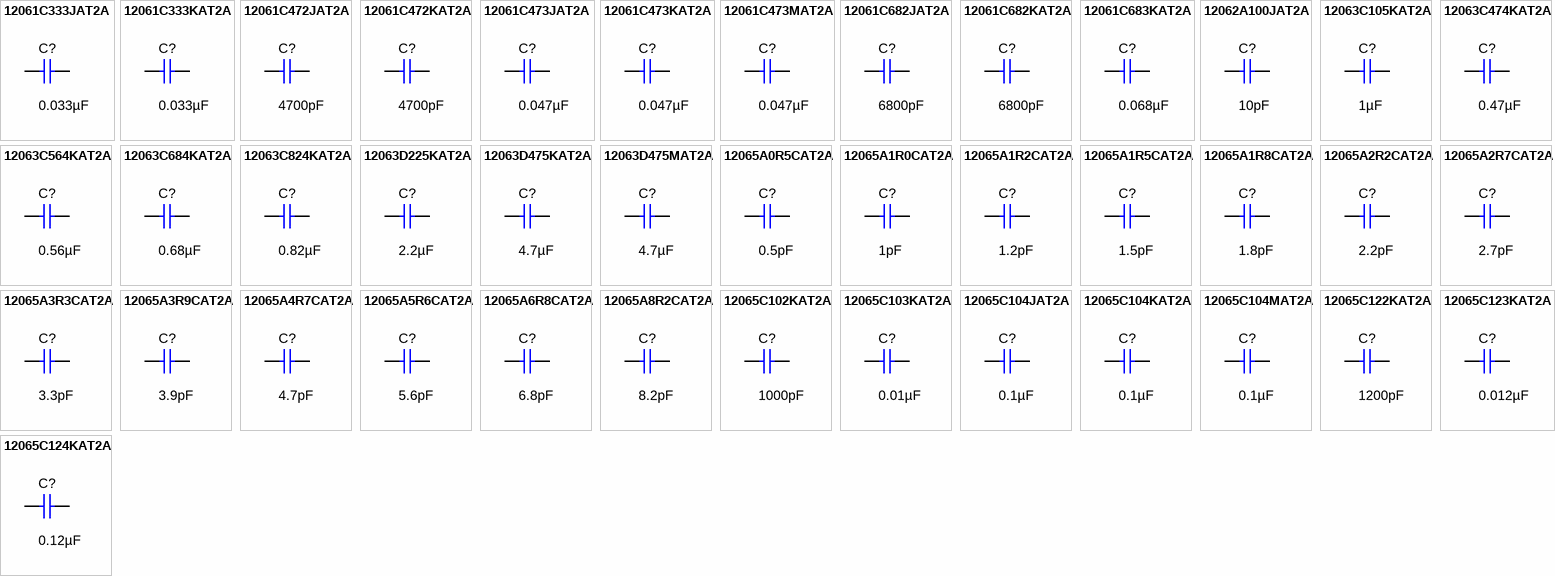
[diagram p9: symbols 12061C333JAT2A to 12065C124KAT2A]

## 12061C333JAT2A
designator C?  ValueDisplayed: 0.033µF  (hidden comment: 12061C333JAT2A)
CAP, CERM, 0.033 µF, 100 V,+/- 5%, X7R, 1206; Manufacturer: AVX; Polarized: N; CompType: Capacitor; Value: 0.033uF; U/M: EA; Cap_F: 0.000000033; Tolerance_%: 5; ESR_ohm: 0.064; Value1: 0.064 ohm; VDC_V: 100; Value2: 100V; TaMin_C: -55; TaMax_C: 125; Cap_Case: 1206; SizeArea_mm2: 5.12; SizeAreaWB_mm2: 10.92; SizeX_mm: 3.2; SizeY_mm: 1.6; SizeZ_mm: 1.35; AEC Category: Q200; Green_Lifecycle: Not Set; Green_REACh: Incomplete
signal-integrity model Cap
simulation model Cap
footprint 1206
footprint 1206M
footprint 1206L
pins: 1, 2

## 12061C333KAT2A
designator C?  ValueDisplayed: 0.033µF  (hidden comment: 12061C333KAT2A)
CAP, CERM, 0.033 µF, 100 V,+/- 10%, X7R, 1206; Manufacturer: AVX; Polarized: N; CompType: Capacitor; Value: 0.033uF; U/M: EA; Cap_F: 0.000000033; Tolerance_%: 10; ESR_ohm: 0.064; Value1: 0.064 ohm; VDC_V: 100; Value2: 100V; TaMin_C: -55; TaMax_C: 125; Cap_Case: 1206; SizeArea_mm2: 5.12; SizeAreaWB_mm2: 10.92; SizeX_mm: 3.2; SizeY_mm: 1.6; SizeZ_mm: 1.35; AEC Category: Q200; Green_Lifecycle: Not Set; Green_REACh: Incomplete
signal-integrity model Cap
simulation model Cap
footprint 1206
footprint 1206M
footprint 1206L
pins: 1, 2

## 12061C472JAT2A
designator C?  ValueDisplayed: 4700pF  (hidden comment: 12061C472JAT2A)
CAP, CERM, 4700 pF, 100 V,+/- 5%, X7R, 1206; Manufacturer: AVX; Polarized: N; CompType: Capacitor; Value: 4700pF; U/M: EA; Cap_F: 0.0000000047; Tolerance_%: 5; ESR_ohm: 0.178; Value1: 0.178 ohm; VDC_V: 100; Value2: 100V; TaMin_C: -55; TaMax_C: 125; Cap_Case: 1206; SizeArea_mm2: 5.12; SizeAreaWB_mm2: 10.92; SizeX_mm: 3.2; SizeY_mm: 1.6; SizeZ_mm: 1.35; AEC Category: Q200; Green_Lifecycle: Not Set; Green_REACh: Incomplete
signal-integrity model Cap
simulation model Cap
footprint 1206
footprint 1206M
footprint 1206L
pins: 1, 2

## 12061C472KAT2A
designator C?  ValueDisplayed: 4700pF  (hidden comment: 12061C472KAT2A)
CAP, CERM, 4700 pF, 100 V,+/- 10%, X7R, 1206; Manufacturer: AVX; Polarized: N; CompType: Capacitor; Value: 4700pF; U/M: EA; Cap_F: 0.0000000047; Tolerance_%: 10; ESR_ohm: 0.178; Value1: 0.178 ohm; VDC_V: 100; Value2: 100V; TaMin_C: -55; TaMax_C: 125; Cap_Case: 1206; SizeArea_mm2: 5.12; SizeAreaWB_mm2: 10.92; SizeX_mm: 3.2; SizeY_mm: 1.6; SizeZ_mm: 1.35; AEC Category: Q200; Green_Lifecycle: Not Set; Green_REACh: Incomplete
signal-integrity model Cap
simulation model Cap
footprint 1206
footprint 1206M
footprint 1206L
pins: 1, 2

## 12061C473JAT2A
designator C?  ValueDisplayed: 0.047µF  (hidden comment: 12061C473JAT2A)
CAP, CERM, 0.047 µF, 100 V,+/- 5%, X7R, 1206; Manufacturer: AVX; Polarized: N; CompType: Capacitor; Value: 0.047uF; U/M: EA; Cap_F: 0.000000047; Tolerance_%: 5; ESR_ohm: 0.054; Value1: 0.054 ohm; VDC_V: 100; Value2: 100V; TaMin_C: -55; TaMax_C: 125; Cap_Case: 1206; SizeArea_mm2: 5.12; SizeAreaWB_mm2: 10.92; SizeX_mm: 3.2; SizeY_mm: 1.6; SizeZ_mm: 1.35; AEC Category: Q200; Green_Lifecycle: Not Set; Green_REACh: Incomplete
signal-integrity model Cap
simulation model Cap
footprint 1206
footprint 1206M
footprint 1206L
pins: 1, 2

## 12061C473KAT2A
designator C?  ValueDisplayed: 0.047µF  (hidden comment: 12061C473KAT2A)
CAP, CERM, 0.047 µF, 100 V,+/- 10%, X7R, 1206; Manufacturer: AVX; Polarized: N; CompType: Capacitor; Value: 0.047uF; U/M: EA; Cap_F: 0.000000047; Tolerance_%: 10; ESR_ohm: 0.054; Value1: 0.054 ohm; VDC_V: 100; Value2: 100V; TaMin_C: -55; TaMax_C: 125; Cap_Case: 1206; SizeArea_mm2: 5.12; SizeAreaWB_mm2: 10.92; SizeX_mm: 3.2; SizeY_mm: 1.6; SizeZ_mm: 1.35; AEC Category: Q200; Green_Lifecycle: Not Set; Green_REACh: Incomplete
signal-integrity model Cap
simulation model Cap
footprint 1206
footprint 1206M
footprint 1206L
pins: 1, 2

## 12061C473MAT2A
designator C?  ValueDisplayed: 0.047µF  (hidden comment: 12061C473MAT2A)
CAP, CERM, 0.047 µF, 100 V,+/- 20%, X7R, 1206; Manufacturer: AVX; Polarized: N; CompType: Capacitor; Value: 0.047uF; U/M: EA; Cap_F: 0.000000047; Tolerance_%: 20; ESR_ohm: 0.054; Value1: 0.054 ohm; VDC_V: 100; Value2: 100V; TaMin_C: -55; TaMax_C: 125; Cap_Case: 1206; SizeArea_mm2: 5.12; SizeAreaWB_mm2: 10.92; SizeX_mm: 3.2; SizeY_mm: 1.6; SizeZ_mm: 1.35; AEC Category: Q200; Green_Lifecycle: Not Set; Green_REACh: Incomplete
signal-integrity model Cap
simulation model Cap
footprint 1206
footprint 1206M
footprint 1206L
pins: 1, 2

## 12061C682JAT2A
designator C?  ValueDisplayed: 6800pF  (hidden comment: 12061C682JAT2A)
CAP, CERM, 6800 pF, 100 V,+/- 5%, X7R, 1206; Manufacturer: AVX; Polarized: N; CompType: Capacitor; Value: 6800pF; U/M: EA; Cap_F: 0.0000000068; Tolerance_%: 5; ESR_ohm: 0.146; Value1: 0.146 ohm; VDC_V: 100; Value2: 100V; TaMin_C: -55; TaMax_C: 125; Cap_Case: 1206; SizeArea_mm2: 5.12; SizeAreaWB_mm2: 10.92; SizeX_mm: 3.2; SizeY_mm: 1.6; SizeZ_mm: 1.35; AEC Category: Q200; Green_Lifecycle: Not Set; Green_REACh: Incomplete
signal-integrity model Cap
simulation model Cap
footprint 1206
footprint 1206M
footprint 1206L
pins: 1, 2

## 12061C682KAT2A
designator C?  ValueDisplayed: 6800pF  (hidden comment: 12061C682KAT2A)
CAP, CERM, 6800 pF, 100 V,+/- 10%, X7R, 1206; Manufacturer: AVX; Polarized: N; CompType: Capacitor; Value: 6800pF; U/M: EA; Cap_F: 0.0000000068; Tolerance_%: 10; ESR_ohm: 0.146; Value1: 0.146 ohm; VDC_V: 100; Value2: 100V; TaMin_C: -55; TaMax_C: 125; Cap_Case: 1206; SizeArea_mm2: 5.12; SizeAreaWB_mm2: 10.92; SizeX_mm: 3.2; SizeY_mm: 1.6; SizeZ_mm: 1.35; AEC Category: Q200; Green_Lifecycle: Not Set; Green_REACh: Incomplete
signal-integrity model Cap
simulation model Cap
footprint 1206
footprint 1206M
footprint 1206L
pins: 1, 2

## 12061C683KAT2A
designator C?  ValueDisplayed: 0.068µF  (hidden comment: 12061C683KAT2A)
CAP, CERM, 0.068 µF, 100 V,+/- 10%, X7R, 1206; Manufacturer: AVX; Polarized: N; CompType: Capacitor; Value: 0.068uF; U/M: EA; Cap_F: 0.000000068; Tolerance_%: 10; ESR_ohm: 0.045; Value1: 0.045 ohm; VDC_V: 100; Value2: 100V; TaMin_C: -55; TaMax_C: 125; Cap_Case: 1206; SizeArea_mm2: 5.12; SizeAreaWB_mm2: 10.92; SizeX_mm: 3.2; SizeY_mm: 1.6; SizeZ_mm: 1.35; AEC Category: Q200; Green_Lifecycle: Not Set; Green_REACh: Incomplete
signal-integrity model Cap
simulation model Cap
footprint 1206
footprint 1206M
footprint 1206L
pins: 1, 2

## 12062A100JAT2A
designator C?  ValueDisplayed: 10pF  (hidden comment: 12062A100JAT2A)
CAP, CERM, 10 pF, 200 V,+/- 5%, C0G/NP0, 1206; Manufacturer: AVX; Polarized: N; CompType: Capacitor; Value: 10pF; U/M: EA; Cap_F: 0.00000000001; Tolerance_%: 5; VDC_V: 200; Value2: 200V; TaMin_C: -55; TaMax_C: 125; Cap_Case: 1206; SizeArea_mm2: 5.12; SizeAreaWB_mm2: 10.92; SizeX_mm: 3.2; SizeY_mm: 1.6; SizeZ_mm: 1.35; AEC Category: Q200; Green_Lifecycle: Active; Green_REACh: Passed
signal-integrity model Cap
simulation model Cap
footprint 1206
footprint 1206M
footprint 1206L
pins: 1, 2

## 12063C105KAT2A
designator C?  ValueDisplayed: 1µF  (hidden comment: 12063C105KAT2A)
CAP, CERM, 1 µF, 25 V,+/- 10%, X7R, 1206; Manufacturer: AVX; Polarized: N; CompType: Capacitor; Value: 1uF; U/M: EA; Cap_F: 0.000001; Tolerance_%: 10; ESR_ohm: 0.013; Value1: 0.013 ohm; VDC_V: 25; Value2: 25V; TaMin_C: -55; TaMax_C: 125; Cap_Case: 1206; SizeArea_mm2: 5.12; SizeAreaWB_mm2: 10.92; SizeX_mm: 3.2; SizeY_mm: 1.6; SizeZ_mm: 1.35; AEC Category: Q200; Green_Lifecycle: Active; Green_REACh: Passed
signal-integrity model Cap
simulation model Cap
footprint 1206
footprint 1206M
footprint 1206L
pins: 1, 2

## 12063C474KAT2A
designator C?  ValueDisplayed: 0.47µF  (hidden comment: 12063C474KAT2A)
CAP, CERM, 0.47 µF, 25 V,+/- 10%, X7R, 1206; Manufacturer: AVX; Polarized: N; CompType: Capacitor; Value: 0.47uF; U/M: EA; Cap_F: 0.00000047; Tolerance_%: 10; ESR_ohm: 0.018; Value1: 0.018 ohm; VDC_V: 25; Value2: 25V; TaMin_C: -55; TaMax_C: 125; Cap_Case: 1206; SizeArea_mm2: 5.12; SizeAreaWB_mm2: 10.92; SizeX_mm: 3.2; SizeY_mm: 1.6; SizeZ_mm: 1.35; AEC Category: Q200; Green_Lifecycle: Active; Green_REACh: Passed
signal-integrity model Cap
simulation model Cap
footprint 1206
footprint 1206M
footprint 1206L
pins: 1, 2

## 12063C564KAT2A
designator C?  ValueDisplayed: 0.56µF  (hidden comment: 12063C564KAT2A)
CAP, CERM, 0.56 µF, 25 V,+/- 10%, X7R, 1206; Manufacturer: AVX; Polarized: N; CompType: Capacitor; Value: 0.56uF; U/M: EA; Cap_F: 0.00000056; Tolerance_%: 10; ESR_ohm: 0.017; Value1: 0.017 ohm; VDC_V: 25; Value2: 25V; TaMin_C: -55; TaMax_C: 125; Cap_Case: 1206; SizeArea_mm2: 5.12; SizeAreaWB_mm2: 10.92; SizeX_mm: 3.2; SizeY_mm: 1.6; SizeZ_mm: 1.35; AEC Category: Q200; Green_Lifecycle: Not Set; Green_REACh: Incomplete
signal-integrity model Cap
simulation model Cap
footprint 1206
footprint 1206M
footprint 1206L
pins: 1, 2

## 12063C684KAT2A
designator C?  ValueDisplayed: 0.68µF  (hidden comment: 12063C684KAT2A)
CAP, CERM, 0.68 µF, 25 V,+/- 10%, X7R, 1206; Manufacturer: AVX; Polarized: N; CompType: Capacitor; Value: 0.68uF; U/M: EA; Cap_F: 0.00000068; Tolerance_%: 10; ESR_ohm: 0.016; Value1: 0.016 ohm; VDC_V: 25; Value2: 25V; TaMin_C: -55; TaMax_C: 125; Cap_Case: 1206; SizeArea_mm2: 5.12; SizeAreaWB_mm2: 10.92; SizeX_mm: 3.2; SizeY_mm: 1.6; SizeZ_mm: 1.35; AEC Category: Q200; Green_Lifecycle: Not Set; Green_REACh: Incomplete
signal-integrity model Cap
simulation model Cap
footprint 1206
footprint 1206M
footprint 1206L
pins: 1, 2

## 12063C824KAT2A
designator C?  ValueDisplayed: 0.82µF  (hidden comment: 12063C824KAT2A)
CAP, CERM, 0.82 µF, 25 V,+/- 10%, X7R, 1206; Manufacturer: AVX; Polarized: N; CompType: Capacitor; Value: 0.82uF; U/M: EA; Cap_F: 0.00000082; Tolerance_%: 10; ESR_ohm: 0.015; Value1: 0.015 ohm; VDC_V: 25; Value2: 25V; TaMin_C: -55; TaMax_C: 125; Cap_Case: 1206; SizeArea_mm2: 5.12; SizeAreaWB_mm2: 10.92; SizeX_mm: 3.2; SizeY_mm: 1.6; SizeZ_mm: 1.35; AEC Category: Q200; Green_Lifecycle: Not Set; Green_REACh: Incomplete
signal-integrity model Cap
simulation model Cap
footprint 1206
footprint 1206M
footprint 1206L
pins: 1, 2

## 12063D225KAT2A
designator C?  ValueDisplayed: 2.2µF  (hidden comment: 12063D225KAT2A)
CAP, CERM, 2.2 µF, 25 V,+/- 10%, X5R, 1206; Manufacturer: AVX; Polarized: N; CompType: Capacitor; Value: 2.2uF; U/M: EA; Cap_F: 0.0000022; Tolerance_%: 10; ESR_ohm: 0.016; Value1: 0.016 ohm; VDC_V: 25; Value2: 25V; TaMin_C: -55; TaMax_C: 85; Cap_Case: 1206; SizeArea_mm2: 5.12; SizeAreaWB_mm2: 10.92; SizeX_mm: 3.2; SizeY_mm: 1.6; SizeZ_mm: 1.35; AEC Category: Q200; Green_Lifecycle: Active; Green_REACh: Passed
signal-integrity model Cap
simulation model Cap
footprint 1206
footprint 1206M
footprint 1206L
pins: 1, 2

## 12063D475KAT2A
designator C?  ValueDisplayed: 4.7µF  (hidden comment: 12063D475KAT2A)
CAP, CERM, 4.7 µF, 25 V,+/- 10%, X5R, 1206; Manufacturer: AVX; Polarized: N; CompType: Capacitor; Value: 4.7uF; U/M: EA; Cap_F: 0.0000047; Tolerance_%: 10; ESR_ohm: 0.01; Value1: 0.01 ohm; VDC_V: 25; Value2: 25V; TaMin_C: -55; TaMax_C: 85; Cap_Case: 1206; SizeArea_mm2: 5.12; SizeAreaWB_mm2: 10.92; SizeX_mm: 3.2; SizeY_mm: 1.6; SizeZ_mm: 1.35; AEC Category: Q200; Green_Lifecycle: Active; Green_REACh: Passed
signal-integrity model Cap
simulation model Cap
footprint 1206
footprint 1206M
footprint 1206L
pins: 1, 2

## 12063D475MAT2A
designator C?  ValueDisplayed: 4.7µF  (hidden comment: 12063D475MAT2A)
CAP, CERM, 4.7 µF, 25 V,+/- 20%, X5R, 1206; Manufacturer: AVX; Polarized: N; CompType: Capacitor; Value: 4.7uF; U/M: EA; Cap_F: 0.0000047; Tolerance_%: 20; ESR_ohm: 0.01; Value1: 0.01 ohm; VDC_V: 25; Value2: 25V; TaMin_C: -55; TaMax_C: 85; Cap_Case: 1206; SizeArea_mm2: 5.12; SizeAreaWB_mm2: 10.92; SizeX_mm: 3.2; SizeY_mm: 1.6; SizeZ_mm: 1.35; AEC Category: Q200; Green_Lifecycle: Not Set; Green_REACh: Incomplete
signal-integrity model Cap
simulation model Cap
footprint 1206
footprint 1206M
footprint 1206L
pins: 1, 2

## 12065A0R5CAT2A
designator C?  ValueDisplayed: 0.5pF  (hidden comment: 12065A0R5CAT2A)
CAP, CERM, 0.5 pF, 50 V,+/- 50%, C0G/NP0, 1206; Manufacturer: AVX; Polarized: N; CompType: Capacitor; Value: 0.5pF; U/M: EA; Cap_F: 0.0000000000005; Tolerance_%: 50; ESR_ohm: 27.39; Value1: 27.39 ohm; Value2: 50V; TaMin_C: -55; TaMax_C: 125; Cap_Case: 1206; SizeArea_mm2: 5.12; SizeAreaWB_mm2: 10.92; SizeX_mm: 3.2; SizeY_mm: 1.6; SizeZ_mm: 1.35; AEC Category: Q200; Green_Lifecycle: Not Set; Green_REACh: Incomplete
signal-integrity model Cap
simulation model Cap
footprint 1206
footprint 1206M
footprint 1206L
pins: 1, 2

## 12065A1R0CAT2A
designator C?  ValueDisplayed: 1pF  (hidden comment: 12065A1R0CAT2A)
CAP, CERM, 1 pF, 50 V,+/- 25%, C0G/NP0, 1206; Manufacturer: AVX; Polarized: N; CompType: Capacitor; Value: 1pF; U/M: EA; Cap_F: 0.000000000001; Tolerance_%: 25; ESR_ohm: 15.566; Value1: 15.566 ohm; VDC_V: 50; Value2: 50V; TaMin_C: -55; TaMax_C: 125; Cap_Case: 1206; SizeArea_mm2: 5.12; SizeAreaWB_mm2: 10.92; SizeX_mm: 3.2; SizeY_mm: 1.6; SizeZ_mm: 1.35; AEC Category: Q200; Green_Lifecycle: Not Set; Green_REACh: Incomplete
signal-integrity model Cap
simulation model Cap
footprint 1206
footprint 1206M
footprint 1206L
pins: 1, 2

## 12065A1R2CAT2A
designator C?  ValueDisplayed: 1.2pF  (hidden comment: 12065A1R2CAT2A)
CAP, CERM, 1.2 pF, 50 V,+/- 21%, C0G/NP0, 1206; Manufacturer: AVX; Polarized: N; CompType: Capacitor; Value: 1.2pF; U/M: EA; Cap_F: 0.0000000000012; Tolerance_%: 21; ESR_ohm: 13.483; Value1: 13.483 ohm; VDC_V: 50; Value2: 50V; TaMin_C: -55; TaMax_C: 125; Cap_Case: 1206; SizeArea_mm2: 5.12; SizeAreaWB_mm2: 10.92; SizeX_mm: 3.2; SizeY_mm: 1.6; SizeZ_mm: 1.35; AEC Category: Q200; Green_Lifecycle: Not Set; Green_REACh: Incomplete
signal-integrity model Cap
simulation model Cap
footprint 1206
footprint 1206M
footprint 1206L
pins: 1, 2

## 12065A1R5CAT2A
designator C?  ValueDisplayed: 1.5pF  (hidden comment: 12065A1R5CAT2A)
CAP, CERM, 1.5 pF, 50 V,+/- 17%, C0G/NP0, 1206; Manufacturer: AVX; Polarized: N; CompType: Capacitor; Value: 1.5pF; U/M: EA; Cap_F: 0.0000000000015; Tolerance_%: 17; ESR_ohm: 11.341; Value1: 11.341 ohm; VDC_V: 50; Value2: 50V; TaMin_C: -55; TaMax_C: 125; Cap_Case: 1206; SizeArea_mm2: 5.12; SizeAreaWB_mm2: 10.92; SizeX_mm: 3.2; SizeY_mm: 1.6; SizeZ_mm: 1.35; AEC Category: Q200; Green_Lifecycle: Not Set; Green_REACh: Incomplete
signal-integrity model Cap
simulation model Cap
footprint 1206
footprint 1206M
footprint 1206L
pins: 1, 2

## 12065A1R8CAT2A
designator C?  ValueDisplayed: 1.8pF  (hidden comment: 12065A1R8CAT2A)
CAP, CERM, 1.8 pF, 50 V,+/- 14%, C0G/NP0, 1206; Manufacturer: AVX; Polarized: N; CompType: Capacitor; Value: 1.8pF; U/M: EA; Cap_F: 0.0000000000018; Tolerance_%: 14; ESR_ohm: 9.868; Value1: 9.868 ohm; VDC_V: 50; Value2: 50V; TaMin_C: -55; TaMax_C: 125; Cap_Case: 1206; SizeArea_mm2: 5.12; SizeAreaWB_mm2: 10.92; SizeX_mm: 3.2; SizeY_mm: 1.6; SizeZ_mm: 1.35; AEC Category: Q200; Green_Lifecycle: Not Set; Green_REACh: Incomplete
signal-integrity model Cap
simulation model Cap
footprint 1206
footprint 1206M
footprint 1206L
pins: 1, 2

## 12065A2R2CAT2A
designator C?  ValueDisplayed: 2.2pF  (hidden comment: 12065A2R2CAT2A)
CAP, CERM, 2.2 pF, 50 V,+/- 11%, C0G/NP0, 1206; Manufacturer: AVX; Polarized: N; CompType: Capacitor; Value: 2.2pF; U/M: EA; Cap_F: 0.0000000000022; Tolerance_%: 11; ESR_ohm: 8.487; Value1: 8.487 ohm; VDC_V: 50; Value2: 50V; TaMin_C: -55; TaMax_C: 125; Cap_Case: 1206; SizeArea_mm2: 5.12; SizeAreaWB_mm2: 10.92; SizeX_mm: 3.2; SizeY_mm: 1.6; SizeZ_mm: 1.35; AEC Category: Q200; Green_Lifecycle: Not Set; Green_REACh: Incomplete
signal-integrity model Cap
simulation model Cap
footprint 1206
footprint 1206M
footprint 1206L
pins: 1, 2

## 12065A2R7CAT2A
designator C?  ValueDisplayed: 2.7pF  (hidden comment: 12065A2R7CAT2A)
CAP, CERM, 2.7 pF, 50 V,+/- 9%, C0G/NP0, 1206; Manufacturer: AVX; Polarized: N; CompType: Capacitor; Value: 2.7pF; U/M: EA; Cap_F: 0.0000000000027; Tolerance_%: 9; ESR_ohm: 7.295; Value1: 7.295 ohm; VDC_V: 50; Value2: 50V; TaMin_C: -55; TaMax_C: 125; Cap_Case: 1206; SizeArea_mm2: 5.12; SizeAreaWB_mm2: 10.92; SizeX_mm: 3.2; SizeY_mm: 1.6; SizeZ_mm: 1.35; AEC Category: Q200; Green_Lifecycle: Not Set; Green_REACh: Incomplete
signal-integrity model Cap
simulation model Cap
footprint 1206
footprint 1206M
footprint 1206L
pins: 1, 2

## 12065A3R3CAT2A
designator C?  ValueDisplayed: 3.3pF  (hidden comment: 12065A3R3CAT2A)
CAP, CERM, 3.3 pF, 50 V,+/- 8%, C0G/NP0, 1206; Manufacturer: AVX; Polarized: N; CompType: Capacitor; Value: 3.3pF; U/M: EA; Cap_F: 0.0000000000033; Tolerance_%: 8; ESR_ohm: 6.304; Value1: 6.304 ohm; VDC_V: 50; Value2: 50V; TaMin_C: -55; TaMax_C: 125; Cap_Case: 1206; SizeArea_mm2: 5.12; SizeAreaWB_mm2: 10.92; SizeX_mm: 3.2; SizeY_mm: 1.6; SizeZ_mm: 1.35; AEC Category: Q200; Green_Lifecycle: Not Set; Green_REACh: Incomplete
signal-integrity model Cap
simulation model Cap
footprint 1206
footprint 1206M
footprint 1206L
pins: 1, 2

## 12065A3R9CAT2A
designator C?  ValueDisplayed: 3.9pF  (hidden comment: 12065A3R9CAT2A)
CAP, CERM, 3.9 pF, 50 V,+/- 6%, C0G/NP0, 1206; Manufacturer: AVX; Polarized: N; CompType: Capacitor; Value: 3.9pF; U/M: EA; Cap_F: 0.0000000000039; Tolerance_%: 6; ESR_ohm: 5.592; Value1: 5.592 ohm; VDC_V: 50; Value2: 50V; TaMin_C: -55; TaMax_C: 125; Cap_Case: 1206; SizeArea_mm2: 5.12; SizeAreaWB_mm2: 10.92; SizeX_mm: 3.2; SizeY_mm: 1.6; SizeZ_mm: 1.35; AEC Category: Q200; Green_Lifecycle: Not Set; Green_REACh: Incomplete
signal-integrity model Cap
simulation model Cap
footprint 1206
footprint 1206M
footprint 1206L
pins: 1, 2

## 12065A4R7CAT2A
designator C?  ValueDisplayed: 4.7pF  (hidden comment: 12065A4R7CAT2A)
CAP, CERM, 4.7 pF, 50 V,+/- 5%, C0G/NP0, 1206; Manufacturer: AVX; Polarized: N; CompType: Capacitor; Value: 4.7pF; U/M: EA; Cap_F: 0.0000000000047; Tolerance_%: 5; ESR_ohm: 4.901; Value1: 4.901 ohm; VDC_V: 50; Value2: 50V; TaMin_C: -55; TaMax_C: 125; Cap_Case: 1206; SizeArea_mm2: 5.12; SizeAreaWB_mm2: 10.92; SizeX_mm: 3.2; SizeY_mm: 1.6; SizeZ_mm: 1.35; AEC Category: Q200; Green_Lifecycle: Not Set; Green_REACh: Incomplete
signal-integrity model Cap
simulation model Cap
footprint 1206
footprint 1206M
footprint 1206L
pins: 1, 2

## 12065A5R6CAT2A
designator C?  ValueDisplayed: 5.6pF  (hidden comment: 12065A5R6CAT2A)
CAP, CERM, 5.6 pF, 50 V,+/- 4%, C0G/NP0, 1206; Manufacturer: AVX; Polarized: N; CompType: Capacitor; Value: 5.6pF; U/M: EA; Cap_F: 0.0000000000056; Tolerance_%: 4; ESR_ohm: 4.337; Value1: 4.337 ohm; VDC_V: 50; Value2: 50V; TaMin_C: -55; TaMax_C: 125; Cap_Case: 1206; SizeArea_mm2: 5.12; SizeAreaWB_mm2: 10.92; SizeX_mm: 3.2; SizeY_mm: 1.6; SizeZ_mm: 1.35; AEC Category: Q200; Green_Lifecycle: Not Set; Green_REACh: Incomplete
signal-integrity model Cap
simulation model Cap
footprint 1206
footprint 1206M
footprint 1206L
pins: 1, 2

## 12065A6R8CAT2A
designator C?  ValueDisplayed: 6.8pF  (hidden comment: 12065A6R8CAT2A)
CAP, CERM, 6.8 pF, 50 V,+/- 4%, C0G/NP0, 1206; Manufacturer: AVX; Polarized: N; CompType: Capacitor; Value: 6.8pF; U/M: EA; Cap_F: 0.0000000000068; Tolerance_%: 4; ESR_ohm: 3.794; Value1: 3.794 ohm; VDC_V: 50; Value2: 50V; TaMin_C: -55; TaMax_C: 125; Cap_Case: 1206; SizeArea_mm2: 5.12; SizeAreaWB_mm2: 10.92; SizeX_mm: 3.2; SizeY_mm: 1.6; SizeZ_mm: 1.35; AEC Category: Q200; Green_Lifecycle: Active; Green_REACh: Passed
signal-integrity model Cap
simulation model Cap
footprint 1206
footprint 1206M
footprint 1206L
pins: 1, 2

## 12065A8R2CAT2A
designator C?  ValueDisplayed: 8.2pF  (hidden comment: 12065A8R2CAT2A)
CAP, CERM, 8.2 pF, 50 V,+/- 3%, C0G/NP0, 1206; Manufacturer: AVX; Polarized: N; CompType: Capacitor; Value: 8.2pF; U/M: EA; Cap_F: 0.0000000000082; Tolerance_%: 3; ESR_ohm: 3.341; Value1: 3.341 ohm; VDC_V: 50; Value2: 50V; TaMin_C: -55; TaMax_C: 125; Cap_Case: 1206; SizeArea_mm2: 5.12; SizeAreaWB_mm2: 10.92; SizeX_mm: 3.2; SizeY_mm: 1.6; SizeZ_mm: 1.35; AEC Category: Q200; Green_Lifecycle: Active; Green_REACh: Passed
signal-integrity model Cap
simulation model Cap
footprint 1206
footprint 1206M
footprint 1206L
pins: 1, 2

## 12065C102KAT2A
designator C?  ValueDisplayed: 1000pF  (hidden comment: 12065C102KAT2A)
CAP, CERM, 1000 pF, 50 V,+/- 10%, X7R, 1206; Manufacturer: AVX; Polarized: N; CompType: Capacitor; Value: 1000pF; U/M: EA; Cap_F: 0.000000001; Tolerance_%: 10; ESR_ohm: 0.427; Value1: 0.427 ohm; VDC_V: 50; Value2: 50V; TaMin_C: -55; TaMax_C: 125; Cap_Case: 1206; SizeArea_mm2: 5.12; SizeAreaWB_mm2: 10.92; SizeX_mm: 3.2; SizeY_mm: 1.6; SizeZ_mm: 1.35; AEC Category: Q200; Green_Lifecycle: Active; Green_REACh: Passed
signal-integrity model Cap
simulation model Cap
footprint 1206
footprint 1206M
footprint 1206L
pins: 1, 2

## 12065C103KAT2A
designator C?  ValueDisplayed: 0.01µF  (hidden comment: 12065C103KAT2A)
CAP, CERM, 0.01 µF, 50 V,+/- 10%, X7R, 1206; Manufacturer: AVX; Polarized: N; CompType: Capacitor; Value: 0.01uF; U/M: EA; Cap_F: 0.00000001; Tolerance_%: 10; ESR_ohm: 0.119; Value1: 0.119 ohm; VDC_V: 50; Value2: 50V; TaMin_C: -55; TaMax_C: 125; Cap_Case: 1206; SizeArea_mm2: 5.12; SizeAreaWB_mm2: 10.92; SizeX_mm: 3.2; SizeY_mm: 1.6; SizeZ_mm: 1.35; AEC Category: Q200; Green_Lifecycle: Active; Green_REACh: Passed
signal-integrity model Cap
simulation model Cap
footprint 1206
footprint 1206M
footprint 1206L
pins: 1, 2

## 12065C104JAT2A
designator C?  ValueDisplayed: 0.1µF  (hidden comment: 12065C104JAT2A)
CAP, CERM, 0.1 µF, 50 V,+/- 5%, X7R, 1206; Manufacturer: AVX; Polarized: N; CompType: Capacitor; Value: 0.1uF; U/M: EA; Cap_F: 0.0000001; Tolerance_%: 5; ESR_ohm: 0.037; Value1: 0.037 ohm; VDC_V: 50; Value2: 50V; TaMin_C: -55; TaMax_C: 125; Cap_Case: 1206; SizeArea_mm2: 5.12; SizeAreaWB_mm2: 10.92; SizeX_mm: 3.2; SizeY_mm: 1.6; SizeZ_mm: 1.35; AEC Category: Q200; Green_Lifecycle: Active; Green_REACh: Passed
signal-integrity model Cap
simulation model Cap
footprint 1206
footprint 1206M
footprint 1206L
pins: 1, 2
